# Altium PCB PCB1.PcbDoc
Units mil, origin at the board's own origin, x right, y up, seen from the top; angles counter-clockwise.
Board outline 6000 x 4000 mil, 2 copper layers (Top Layer, Bottom Layer); 65 components, 34 nets, 257 pads, 0 vias.
Unrouted connection lines stored in the file: 196.
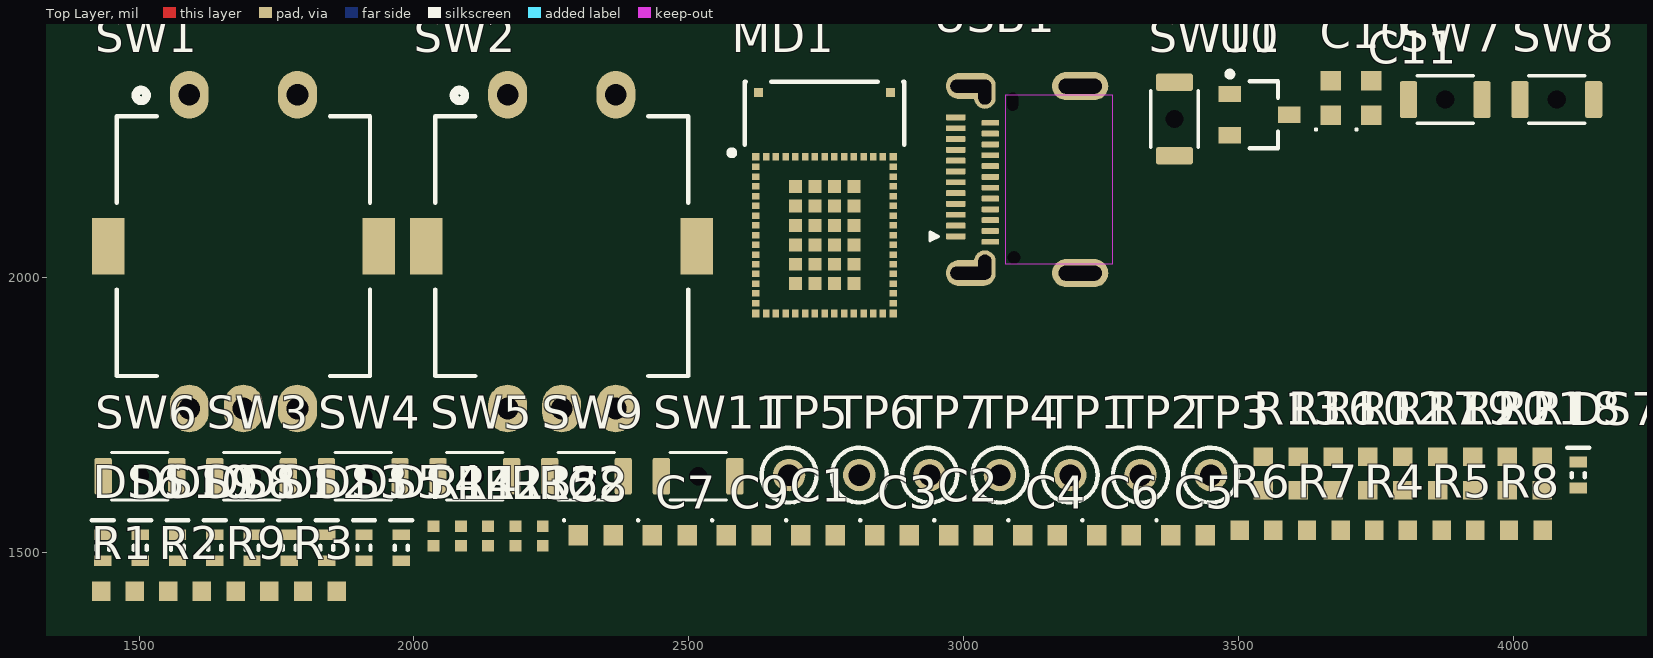
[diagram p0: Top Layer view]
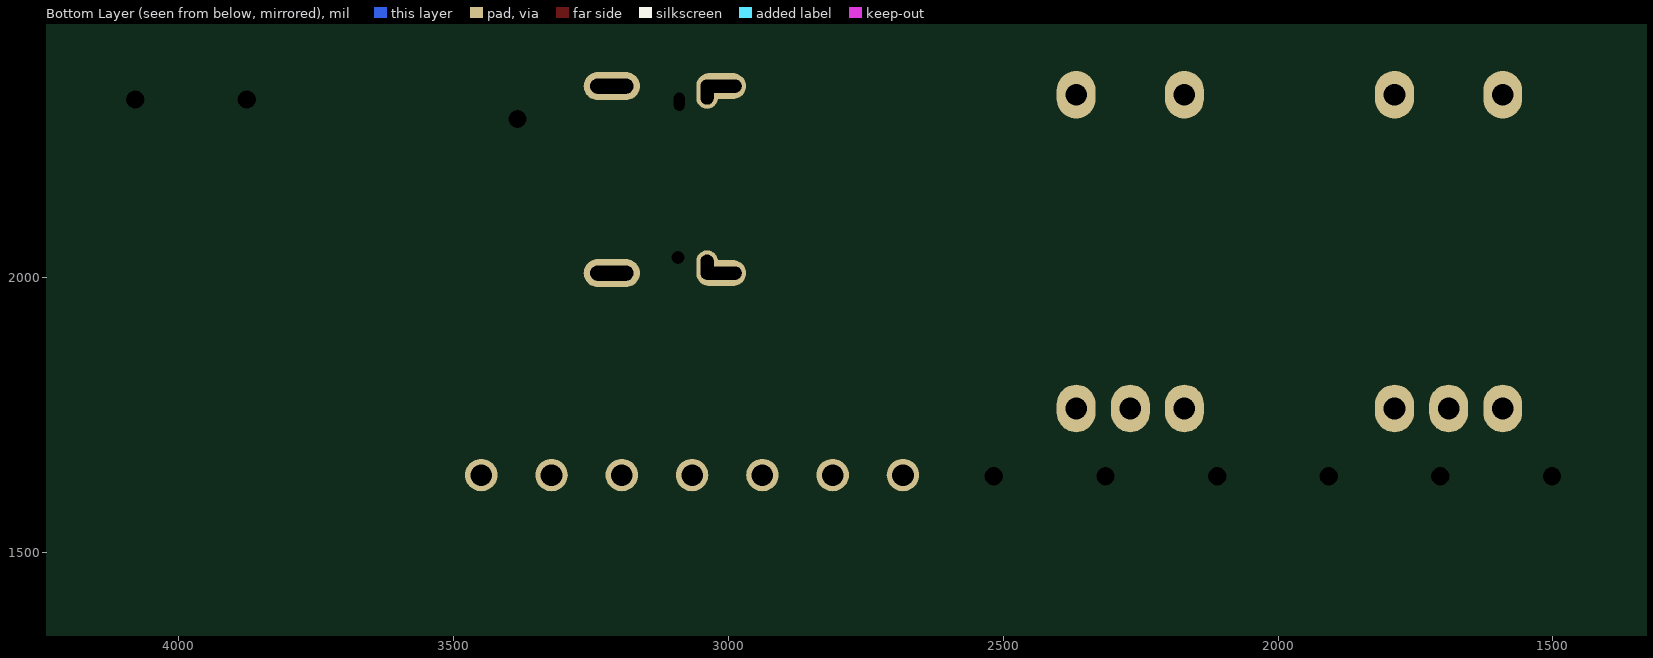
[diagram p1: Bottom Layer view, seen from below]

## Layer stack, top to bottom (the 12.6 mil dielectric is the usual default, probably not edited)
Top Solder: solder mask 0.4, Solder Resist, Dk 3.5
Top Layer: signal copper 1.4
Dielectric 1: dielectric 12.6, FR-4, Dk 4.8
Bottom Layer: signal copper 1.4
Bottom Solder: solder mask 0.4, Solder Resist, Dk 3.5

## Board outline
1000,1000 7000,1000 7000,5000 1000,5000

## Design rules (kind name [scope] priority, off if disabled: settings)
Clearance [All] p1: gap=10 ignorepadtopadclearanceinfootprint=FALSE
PolygonConnect [All] p1: connectstyle=Relief reliefconductorwidth=10 reliefentries=4 polygonreliefangle="90 Angle" airgapwidth=10
RoutingVias [All] p1: holewidth=28 width=50 viastyle="Through Hole" minholewidth=28 minwidth=50 maxholewidth=28 maxwidth=50
SolderMaskExpansion [All] p1: expansion=4 istentingtop=FALSE
SupplyNets "Schematic Supply Nets_2" [InNet('GND')] p1: voltage=0.000
SupplyNets "Schematic Supply Nets_1" [InNet('VBUS')] p2: voltage=0.000
SupplyNets "Schematic Supply Nets" [InNet('+3.3V')] p3: voltage=0.000
Width [All] p1: maxlimit=10 minlimit=10 preferedwidth=10
30 further rules are at their usual default settings.

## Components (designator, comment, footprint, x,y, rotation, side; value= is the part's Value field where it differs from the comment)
C1 "10uF" C0603 2734.78,1531.33 r0 top
C2 "10uF" C0603 3004.2,1531.33 r0 top
C3 "1nF" C0603 2869.49,1531.33 r0 top
C4 "1nF" C0603 3138.92,1531.33 r0 top
C5 "1nF" C0603 3408.34,1531.33 r0 top
C6 "1nF" C0603 3273.63,1531.33 r0 top
C7 "1nF" C0603 2465.35,1531.33 r0 top
C8 "10uF" C0603 2330.63,1531.33 r0 top
C9 "1nF" C0603 2600.06,1531.33 r0 top
C10 "10uF" C0603 3668.26,2326.79 r90 top
C11 "0.1uF" C0603 3741.95,2326.79 r90 top value=100nF
DS1 "XL-1608UBC-06A" LED0603 1705.43,1508.38 r90 top
DS2 "XL-1608UBC-06A" LED0603 1773.31,1508.38 r90 top
DS3 "XL-1608UBC-06A" LED0603 1841.18,1508.38 r90 top
DS4 "XL-1608UBC-06A" LED0603 1976.93,1508.38 r90 top
DS5 "XL-1608UBC-06A" LED0603 1909.06,1508.38 r90 top
DS6 "XL-1608UBC-06A" LED0603 1433.94,1508.38 r90 top
DS7 "XL-1608SURC-06" LED0603 4118.38,1640.58 r90 top
DS8 "XL-1608UGC-06A" LED0603 1637.56,1508.38 r90 top
DS9 "XL-1608UBC-06A" LED0603 1569.68,1508.38 r90 top
DS10 "XL-1608UBC-06A" LED0603 1501.81,1508.38 r90 top
MD1 "STM32WB5MMGH6TR" FP-STM32WB5MMGH6TR-MFG 2747,2138.37 r0 top
R1 "5.1K" R0603 1461.24,1429.2 r0 top
R2 "5.1K" R0603 1583.73,1429.2 r0 top
R3 "5.1K" R0603 1828.71,1429.2 r0 top
R4 "5.1K" R0603 3777.78,1540.6 r0 top
R5 "5.1K" R0603 3900.27,1540.6 r0 top
R6 "5.1K" R0603 3532.8,1540.6 r0 top
R7 "5.1K" R0603 3655.29,1540.6 r0 top
R8 "5.1K" R0603 4022.75,1540.6 r0 top
R9 "5.1K" R0603 1706.22,1429.2 r0 top
R10 "5.1K" R0603 3672.13,1643.28 r90 top
R11 "NC" R0402 2085.35,1529.77 r90 top
R12 "5.1K" R0603 3735.56,1643.28 r90 top
R13 "5.1K" R0603 3545.26,1643.28 r90 top
R14 "0R" R0402 2035.69,1529.77 r90 top
R15 "0R" R0402 2184.65,1529.77 r90 top
R16 "5.1K" R0603 3608.69,1643.28 r90 top
R17 "5.1K" R0603 3798.99,1643.28 r90 top
R18 "5.1K" R0603 4052.72,1643.28 r90 top
R19 "5.1K" R0603 3862.42,1643.28 r90 top
R20 "5.1K" R0603 3925.86,1643.28 r90 top
R21 "5.1K" R0603 3989.29,1643.28 r90 top
R22 "0R" R0402 2234.31,1529.77 r90 top
R23 "0R" R0402 2135,1529.77 r90 top
SW1 "EC11L1525G01" EC11L1525G01 1689.59,2057.1 r0 top
SW2 "EC11L1525G01" EC11L1525G01 2268.77,2057.1 r0 top
SW3 "B3U-1000P-B" OMRON-B3U-1000P-2-B_V 1704.61,1638.42 r0 top
SW4 "B3U-1000P-B" OMRON-B3U-1000P-2-B_V 1907.68,1638.42 r0 top
SW5 "B3U-1000P-B" OMRON-B3U-1000P-2-B_V 2110.75,1638.42 r0 top
SW6 "B3U-1000P-B" OMRON-B3U-1000P-2-B_V 1501.54,1638.42 r0 top
SW7 "B3U-1000P-B" OMRON-B3U-1000P-2-B_V 3876.18,2323.9 r0 top
SW8 "B3U-1000P-B" OMRON-B3U-1000P-2-B_V 4079.25,2323.9 r0 top
SW9 "B3U-1000P-B" OMRON-B3U-1000P-2-B_V 2313.82,1638.42 r0 top
SW10 "B3U-1000P-B" OMRON-B3U-1000P-2-B_V 3383.56,2288.46 r90 top
SW11 "B3U-1000P-B" OMRON-B3U-1000P-2-B_V 2516.89,1638.42 r0 top
TP1 "5003" KSTN-5003 3193.86,1640.58 r0 top
TP2 "5003" KSTN-5003 3321.73,1640.58 r0 top
TP3 "5003" KSTN-5003 3449.61,1640.58 r0 top
TP4 "5003" KSTN-5003 3065.98,1640.58 r0 top
TP5 "5003" KSTN-5003 2682.36,1640.58 r0 top
TP6 "5003" KSTN-5003 2810.24,1640.58 r0 top
TP7 "5003" KSTN-5003 2938.11,1640.58 r0 top
U1 "AP2210N-3.3TRG1" SOT23-3 3538.46,2296.34 r0 top
USB1 "DX07S024JJ3R1300" JAE-DX07S024JJ3_V 3091.91,2178.23 r90 top

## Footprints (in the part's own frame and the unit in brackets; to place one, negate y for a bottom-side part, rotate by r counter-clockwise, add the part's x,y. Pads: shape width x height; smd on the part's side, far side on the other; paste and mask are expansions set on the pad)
C0603 [mm] "Chip Capacitor, 2-Leads, Body 1.60x0.80mm, IPC Medium Density"
  rect 0.9x0.95 smd: 1(-0.8,0) 2(0.8,0)
  silkscreen extent -1.51,0.64 -1.41,0.74, body extent -0.85,-0.45 0.85,0.45, height 0.6
EC11L1525G01 [mm]
  oval 1.8x2.2 hole 1: 1(-2.5,7) 2(2.5,7) 3(2.5,-7.5) 4(0,-7.5) 5(-2.5,-7.5)
  rect 1.5x2.6 smd: 6(-6.25,0) 7(6.25,0)
  silkscreen extent -5.85,-6 5.85,7.22
FP-STM32WB5MMGH6TR-MFG [mm]
  rect 0.35x0.35 smd paste+0 mask+0: 1(-3.175,2.075) 17(-3.175,-5.175) 31(3.175,-5.175) 47(3.175,2.075)
  rect 0.35x0.3 smd paste+0 mask+0: 2(-3.175,1.6) 3(-3.175,1.15) 4(-3.175,0.7) 5(-3.175,0.25) 6(-3.175,-0.2) 7(-3.175,-0.65) 8(-3.175,-1.1) 9(-3.175,-1.55) 10(-3.175,-2) 11(-3.175,-2.45) 12(-3.175,-2.9) 13(-3.175,-3.35) 14(-3.175,-3.8) 15(-3.175,-4.25) 16(-3.175,-4.7) 32(3.175,-4.7) 33(3.175,-4.25) 34(3.175,-3.8) 35(3.175,-3.35) 36(3.175,-2.9) 37(3.175,-2.45) 38(3.175,-2) 39(3.175,-1.55) 40(3.175,-1.1) 41(3.175,-0.65) 42(3.175,-0.2) 43(3.175,0.25) 44(3.175,0.7) 45(3.175,1.15) 46(3.175,1.6)
  rect 0.3x0.35 smd paste+0 mask+0: 18(-2.7,-5.175) 19(-2.25,-5.175) 20(-1.8,-5.175) 21(-1.35,-5.175) 22(-0.9,-5.175) 23(-0.45,-5.175) 24(0,-5.175) 25(0.45,-5.175) 26(0.9,-5.175) 27(1.35,-5.175) 28(1.8,-5.175) 29(2.25,-5.175) 30(2.7,-5.175) 48(2.7,2.075) 49(2.25,2.075) 50(1.8,2.075) 51(1.35,2.075) 52(0.9,2.075) 53(0.45,2.075) 54(0,2.075) 55(-0.45,2.075) 56(-0.9,2.075) 57(-1.35,2.075) 58(-1.8,2.075) 59(-2.25,2.075) 60(-2.7,2.075)
  rect 0.6x0.6 smd paste+0 mask+0: 61(-1.35,0.7) 62(-1.35,-0.2) 63(-1.35,-1.1) 64(-1.35,-2) 65(-1.35,-2.9) 66(-1.35,-3.8) 67(-0.45,-3.8) 68(0.45,-3.8) 69(1.35,-3.8) 70(1.35,-2.9) 71(1.35,-2) 72(1.35,-1.1) 73(1.35,-0.2) 74(1.35,0.7) 75(0.45,0.7) 76(-0.45,0.7) 77(-0.45,-0.2) 78(-0.45,-1.1) 79(-0.45,-2) 80(-0.45,-2.9) 81(0.45,-2.9) 82(0.45,-2) 83(0.45,-1.1) 84(0.45,-0.2)
  rect 0.43x0.43 smd paste+0 mask+0: 85(-3.05,5.035) 86(3.05,5.035)
  silkscreen extent -4.41,2.13 3.69,5.54, body extent -4.19,-6.04 4.19,6.04, height 0.25
JAE-DX07S024JJ3_V [mm] "THD, 24-Leads, Body 8.17x8.94mm, Pitch 0.5mm"
  oval 1.2x2.3 hole 0.6 slot 1.9 at 90 deg: 1(-4.32,2) 2(4.32,2)
  oval 1.5x1 hole 0.6 slot 1.1 at 0 deg: 1(-4.02,1.35) 2(4.02,1.35)
  oval 1.3x2.6 hole 0.7 slot 2 at 90 deg: 3(-4.32,-3.05) 4(4.32,-3.05)
  rrect25% 0.27x0.9 smd: A1(-2.625,2.7) A2(-2.125,2.7) A3(-1.625,2.7) A4(-1.125,2.7) A5(-0.625,2.7) A6(-0.125,2.7) A7(0.375,2.7) A8(0.875,2.7) A9(1.375,2.7) A10(1.875,2.7) A11(2.375,2.7) A12(2.875,2.7)
  rrect25% 0.27x0.8 smd: B1(2.625,1.1) B2(2.125,1.1) B3(1.625,1.1) B4(1.125,1.1) B5(0.625,1.1) B6(0.125,1.1) B7(-0.375,1.1) B8(-0.875,1.1) B9(-1.375,1.1) B10(-1.875,1.1) B11(-2.375,1.1) B12(-2.875,1.1)
  round 0 hole 0.6 unplated: H1(-3.6,0)
  round 0 hole 0.5 slot 0.85 at 0 deg unplated: H2(3.6,0.065)
  Top Layer keep-out region: -3.9,-4.55 3.9,-4.55 3.9,0.4 -3.9,0.4
  silkscreen extent -2.83,3.49 -2.43,3.89, body extent -4.47,-5.35 4.47,2.8, height 3.16
KSTN-5003 [mm] "Test Point, Through Hole, Dia 2.54mm"
  round 1.5 hole 1: 1(0,0)
  silkscreen extent -1.27,-1.27 1.27,1.27, body extent -1.27,-1.27 1.27,1.27, height 4.57
LED0603 [mm] "Chip Diode, 2-Leads, Body 1.65x0.85mm, IPC Medium Density"
  rect 0.5x0.8 smd: 1(-0.6,0) 2(0.6,0)
  silkscreen extent -0.1,-0.51 1.27,0.51, body extent -0.85,-0.45 0.85,0.45, height 0.6
OMRON-B3U-1000P-2-B_V [mm] "SMT, 2-Leads, Body 3x2.5mm"
  rrect25% 0.8x1.7 smd: 1(-1.7,0) 2(1.7,0)
  round 0 hole 0.85 unplated: H1(0,0)
  silkscreen extent -1.3,-1.1 1.3,1.1, body extent -2,-1.25 2,1.25, height 1.6
R0402 [mm] "Chip Resistor, 2-Leads, Body 1.00x0.50mm, IPC Medium Density"
  rect 0.55x0.55 smd: 1(-0.45,0) 2(0.45,0)
  body extent -0.53,-0.27 0.53,0.28, height 0.4
R0603 [mm] "Chip Resistor, 2-Leads, Body 1.60x0.80mm, IPC Medium Density"
  rect 0.85x0.9 smd: 1(-0.775,0) 2(0.775,0)
  body extent -0.85,-0.45 0.85,0.45, height 0.6
SOT23-3 [mm] "SOT23, 3-Leads, Body 2.96x2.83mm, Pitch 0.95mm, IPC Medium Density"
  rect 1.05x0.75 smd: 1(-1.375,0.95) 2(-1.375,-0.95) 3(1.375,0)
  silkscreen extent -1.5,-1.55 0.85,2, body extent -1.5,-1.55 1.5,1.55, height 1.5

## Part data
C1 C2 C8 C10: library part C0603_10U, "CAP CER 10UF 35V X5R 0603", Case/Package=0603, Manufacturer=Murata, Part Number=GRM188R6YA106MA73D, Voltage Rating=35V
C3 C4 C5 C6 C7 C9: library part C0603-1N, "CAP CER 1000PF 50V C0G/NP0 0603", Case/Package=0603, Manufacturer="Murata Electronics", Part Number=GRM1885C1H102JA01D, Voltage Rating=50V
C11: library part C0603-0.1U, "CAP CER 0.1UF 16V X7R 0603", Case/Package=0603, Manufacturer="Murata Electronics", Part Number=GCJ188R71C104KA01D, Voltage Rating=16V
DS1 DS2 DS3 DS4 DS5 DS6 DS9 DS10: "CHIP LED 0603 BLUE SMD", Case/Package=0603, Colour=Blue, Manufacturer=XINGLIGHT
DS7: "CHIP LED 0603 RED SMD", Case/Package=0603, Colour=Red, Manufacturer=XINGLIGHT
DS8: "CHIP LED 0603 GREEN SMD", Case/Package=0603, Colour=Green, Manufacturer=XINGLIGHT
MD1: "ULTRA-LOW-POWER DUAL CORE ARM CO", Manufacturer=STMicroelectronics, Part Number=PX32WB5MMGH6TR
R1 R2 R3 R4 R5 R6 R7 R8 R9 R10 R12 R13 R16 R17 R18 R19 R20 R21: library part R0603-5.1K, "RES 5.1K OHM 1% 1/10W 0603", Case/Package=0603, Manufacturer=Yageo, Part Number=RC0603FR-075K1L
R11: library part R0402-NC, "RES NC 0402", Case/Package=0402
R14 R15 R22 R23: library part R0402-0R, "RES 0 OHM JUMPER 1/16W 0402", Case/Package=0402, Manufacturer=Yageo, Part Number=RC0402FR-070RL
SW1 SW2: "Plugin Rotary Encoders ROHS", Manufacturer=ALPSALPINE
SW3 SW4 SW5 SW6 SW7 SW8 SW9 SW10 SW11: "Ultra-small Surface-mounting Tactile Switches with High Contact Reliability, SPST-NO, -25 to 70 degC, 2-Pin SMD, RoHS, Tape and Reel", Manufacturer=Omron, Voltage Rating=12V
TP1 TP2 TP3 TP4 TP5 TP6 TP7: library part CMP-002-00037-2, "Test Point, Orange, Height 4.6 mm, Tail Length 3 mm, 1-Pin THD, RoHS", Colour=Orange, Manufacturer=Keystone, Package Description="1-Pin Through Hole Device, Dia 2.54 mm", Package Quantity=10
U1: "IC REG LINEAR 3.3V 300MA SOT23-3", Case/Package=SOT23-3, Manufacturer="Diodes Incorporated"
USB1: "USB-C Connector, 20 V, 1.25 A, -30 to 80 degC, RoHS, Tape and Reel", Manufacturer="JAE Electronics"

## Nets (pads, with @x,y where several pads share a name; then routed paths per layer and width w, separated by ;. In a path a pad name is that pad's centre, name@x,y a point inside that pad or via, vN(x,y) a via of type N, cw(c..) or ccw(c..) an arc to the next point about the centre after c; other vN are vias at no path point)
+3.3V: C2.2 C8.2 C10.2 DS7.1 MD1.4 MD1.6 MD1.15 MD1.17 R1.2 R2.2 R3.2 R4.2 R7.1 R8.1 R9.1 R10.1 R12.1 R13.1 R16.1 R17.1 R20.1 R21.1 TP1.1 U1.2
CH1OFF: C7.2 MD1.28 R7.2 SW1.1 SW8.1
CH1ON: MD1.8 SW3.1
CH2OFF: C3.2 MD1.30 R2.1 SW1.5 SW10.1
CH2ON: C4.2 MD1.33 R1.1 SW1.3 SW5.1
CH3OFF: C6.2 MD1.35 R3.1 SW2.3 SW9.1
CH3ON: MD1.43 SW4.1
CH4OFF: C9.2 MD1.37 R8.2 SW2.1 SW11.1
CH4ON: C5.2 MD1.41 R4.1 SW2.5 SW6.1
FR: MD1.24 SW7.1
GND: C1.1 C2.1 C3.1 C4.1 C5.1 C6.1 C7.1 C8.1 C9.1 C10.1 C11.1 DS1.2 DS2.2 DS3.2 DS4.2 DS5.2 DS6.2 DS8.2 DS9.2 DS10.2 MD1.1 MD1.2 MD1.3 MD1.5 MD1.7 MD1.9 MD1.11 MD1.12 MD1.13 MD1.14 MD1.16 MD1.18 MD1.19 MD1.20 MD1.21 MD1.23 MD1.27 MD1.29 MD1.31 MD1.32 MD1.34 MD1.36 MD1.38 MD1.40 MD1.42 MD1.44 MD1.45 MD1.46 MD1.47 MD1.48 MD1.49 MD1.50 MD1.51 MD1.52 MD1.53 MD1.54 MD1.55 MD1.56 MD1.57 MD1.58 MD1.59 MD1.60 MD1.61 MD1.62 MD1.63 MD1.64 MD1.65 MD1.71 MD1.72 MD1.73 MD1.74 MD1.75 MD1.76 MD1.77 MD1.78 MD1.79 MD1.80 MD1.81 MD1.82 MD1.83 MD1.84 MD1.85 MD1.86 R5.1 R6.2 R11.2 R14.2 R15.2 R22.2 R23.2 SW1.2 SW1.4 SW1.6 SW1.7 SW2.2 SW2.4 SW2.6 SW2.7 SW3.2 SW4.2 SW5.2 SW6.2 SW7.2 SW8.2 SW9.2 SW10.2 SW11.2 TP2.1 TP7.1 U1.1 USB1.1 USB1.2 USB1.3 USB1.4 USB1.A1 USB1.A12 USB1.B1 USB1.B12
LED: MD1.22 R18.1 R19.1
N0: MD1.68 R22.1
N1: MD1.69 R23.1
NetDS1_1: DS1.1 R9.2
NetDS2_1: DS2.1 R10.2
NetDS3_1: DS3.1 R12.2
NetDS4_1: DS4.1 R13.2
NetDS5_1: DS5.1 R16.2
NetDS6_1: DS6.1 R17.2
NetDS7_2: DS7.2 R18.2
NetDS8_1: DS8.1 R19.2
NetDS9_1: DS9.1 R20.2
NetDS10_1: DS10.1 R21.2
NetR5_2: R5.2 USB1.A5
NetR6_1: R6.1 USB1.B5
NRST: C11.2 MD1.10 TP5.1
S0: MD1.66 R14.1
S1: MD1.67 R15.1
S/C: MD1.70 R11.1
SWCLK: MD1.26 TP4.1
SWDIO: MD1.25 TP3.1
TX: MD1.39 TP6.1
VBUS: C1.2 U1.3 USB1.A4 USB1.A9 USB1.B4 USB1.B9
pads on no net: SW3.H1 SW4.H1 SW5.H1 SW6.H1 SW7.H1 SW8.H1 SW9.H1 SW10.H1 SW11.H1 USB1.A2 USB1.A3 USB1.A6 USB1.A7 USB1.A8 USB1.A10 USB1.A11 USB1.B2 USB1.B3 USB1.B6 USB1.B7 USB1.B8 USB1.B10 USB1.B11 USB1.H1 USB1.H2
